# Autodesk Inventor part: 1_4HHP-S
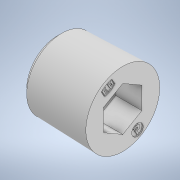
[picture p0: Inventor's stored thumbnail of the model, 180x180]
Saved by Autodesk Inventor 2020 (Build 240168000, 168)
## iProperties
Created: 2019-12
Part Number: 1_4HHP-S
Material: Generico
Description: STEP AP203
Document SubType Name: Modeling
Designer: carlo
Density: 1 g/cm^3
Appearance: Default
DataBaseUnit: MM
Title: p:/temp/worker_142/temp/exporttempdir_4864_1451_vmub3/format_0/Adapters Hexagon socket plug 1_4HHP-S.stp
Revision Number: NONE
Sending System: PARTsolutions
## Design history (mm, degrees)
feature "_Adapters Hexagon socket plug 1_4HHP-S"
node "Solido1"
